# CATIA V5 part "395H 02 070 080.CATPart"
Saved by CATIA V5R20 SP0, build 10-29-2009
Part number: Part1
Source: Unknown
Bounding box of the stored display mesh (mm): x -36.5 to 36.5, y -36.5 to 36.5, z -41 to 41
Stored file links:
  C:\Users\Utente\Desktop\3D files 395H FORD\395H 02 070 080.CATPart
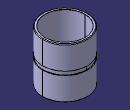
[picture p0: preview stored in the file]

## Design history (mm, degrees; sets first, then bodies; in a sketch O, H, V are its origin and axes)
Body1 (main body)
  Solid1 "PartBody": solid without history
